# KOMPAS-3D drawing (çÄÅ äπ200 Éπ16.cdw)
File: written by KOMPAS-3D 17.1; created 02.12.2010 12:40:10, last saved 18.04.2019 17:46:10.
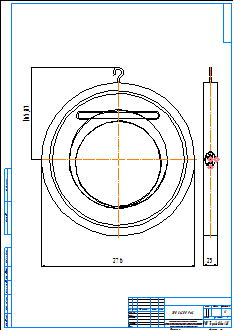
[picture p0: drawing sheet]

Sheet 1: A2, portrait

Title block, sheet 1: name: ЗОП Ду200 Ру16; material: Внимание! Данный продукт является объектом авторского права ООО «Торговый Дом АДЛ». / Запрещается изменение, копирование, распространение / (в том числе путем копирования на другие сайты и ресурсы в Интернете) / или любое иное использование информации и объектов без предварительного / согласия правообладателя (ООО «Торговый Дом АДЛ»).; scale: 1:1; sheets: 1; organisation: ООО "Торговый дом АДЛ"; sheet format: A2; stored path: \\adlc.lan\data\АДЛ_ПКД\3D-модели\ADL production\Клапаны обратные ГРАНЛОК\ЗОП\KOMPAS 2D\ЗОП Ду200 Ру16.cdw

Views: Спереди 1, Проекционный вид 2
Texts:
  bsv
  adl
Dimensions and other numbers on the sheet: 276; 25; 165,87; 1:1; 1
